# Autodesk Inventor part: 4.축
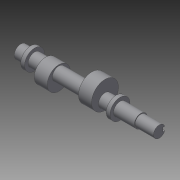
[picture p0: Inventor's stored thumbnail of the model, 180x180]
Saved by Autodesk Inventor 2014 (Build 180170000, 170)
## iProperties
Created: 2014-12
Part Number: 4.축
Material: 일반
Document SubType Name: Modeling
Designer: Owner
Density: 1 g/cm^3
Appearance: 기본값
Author: Owner
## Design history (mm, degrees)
sketch "스케치2"
  geometry: L1 (-90, 0)-(90, 0); L2 (-90, 0)-(-90, 7.5); L3 (-90, 7.5)-(-66, 7.5); L4 (-66, 7.5)-(-66, 8.5); L5 (-66, 8.5)-(-39, 8.5); L6 (-39, 8.5)-(-39, 13); L7 (-39, 13)-(-34, 13); L8 (-34, 13)-(-34, 8.5); L9 (-34, 8.5)-(72, 8.5); L10 (72, 8.5)-(72, 13); L11 (72, 13)-(77, 13); L12 (77, 13)-(77, 8.5); L13 (77, 8.5)-(90, 8.5); L14 (90, 8.5)-(90, 0); 2 further points
  constraints: 28 end point, 11 parallel, 2 coincident, 2 perpendicular, 1 horizontal, 1 midpoint
  dimensions: "d9" = 180 distance of L1.end L1.start; "d10" = 15 diameter of L3 L1; "d11" = 17 diameter of L5 L1; "d12" = 24 distance between parallel lines of L2 L4; "d13" = 27 distance between parallel lines of L4 L6; "d14" = 26 diameter of L7 L1; "d15" = 17 diameter of L9 L1; "d16" = 17 diameter of L13 L1; "d17" = 5 distance between parallel lines of L6 L8; "d18" = 26 diameter of L11 L1; "d19" = 5 distance between parallel lines of L10 L12; "d20" = 13 distance between parallel lines of L14 L12
revolve "회전1" sketch "스케치2" stored, may be unused: angle "d21" = 90 deg
node "작업 평면1"
sketch "스케치3"
  geometry: L1 (-90, -7.5)-(-90, 7.5) reference; L2 (-90, 2.5)-(-72.5, 2.5); L3 (-90, -2.5)-(-72.5, -2.5); A1 r 2.5 centre (-72.5, 0) between (-72.5, -2.5) and (-72.5, 2.5); 2 further points
  constraints: 4 end point, 2 point on circle, 2 point on line, 1 centre point, 1 horizontal alignment, 1 midpoint, 1 perpendicular, 1 tangent
  dimensions: "d23" = 5 diameter of A1; "d24" = 5 distance between parallel lines of L3 L2; "d25" = 17.5 distance from line of L1 A1.centre
extrude "돌출1" cut sketch "스케치3" distance "d26" = 3; taper "d27" = 0 deg
sketch "스케치4"
  geometry: L1 (-19.5, 6)-(-2.5, 6); L2 (-34, -8.5)-(72, -8.5) reference; L3 (-34, 8.5)-(72, 8.5) reference; L4 (-19.5, 6)-(-19.5, 23.5); L5 (-19.5, 23.5)-(-2.5, 23.5); L6 (-2.5, 23.5)-(-2.5, 6); L7 (-90, -7.5)-(-90, 7.5) reference; 3 further points
  constraints: 8 end point, 2 parallel, 2 perpendicular, 1 horizontal
  dimensions: "d28" = 6 distance from line of point (0, 0) L1; "d29" = 17 distance of L1.end L1.start; "d30" = 35 diameter of L5 L1; "d31" = 87.5 distance between parallel lines of L6 L7
revolve "회전2" sketch "스케치4" stored, may be unused: angle "d32" = 90 deg
sketch "스케치5"
  geometry: L1 (40.5, -5)-(57.5, -5); L2 (-2.5, 8.5)-(72, 8.5) reference; L3 (-2.5, -8.5)-(72, -8.5) reference; L4 (40.5, -5)-(40.5, 10); L5 (40.5, 10)-(57.5, 10); L6 (57.5, 10)-(57.5, -5); L7 (90, -8.5)-(90, 8.5) reference; 1 further point
  constraints: 8 end point, 3 perpendicular, 1 horizontal, 1 parallel
  dimensions: "d33" = 5 distance from line of point (0, 0) L1; "d34" = 17 distance of L1.end L1.start; "d35" = 49.5 distance between parallel lines of L7 L4; "d36" = 30 diameter of L5 L1
revolve "회전3" sketch "스케치5" stored, may be unused: angle "d37" = 90 deg
node "솔리드1"
other parameters: "d22" = 7.5
